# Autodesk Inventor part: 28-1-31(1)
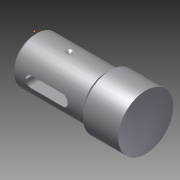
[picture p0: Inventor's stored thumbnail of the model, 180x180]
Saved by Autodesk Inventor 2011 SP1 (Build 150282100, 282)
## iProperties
Created: 2014-01
Part Number: 28-1-31(1)
Document SubType Name: Modeling
Designer: Administrator
Density: 1 g/cm^3
Author: Administrator
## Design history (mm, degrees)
sketch "草图1"
  geometry: L1 (0, 0)-(0, 9); L2 (0, 9)-(1.414, 10.414); L3 (1.414, 10.414)-(32.414, 10.414); L4 (32.414, 10.414)-(32.414, 8.414); L5 (32.414, 8.414)-(34.414, 8.414); L6 (34.414, 8.414)-(34.414, 12.414); L7 (34.414, 12.414)-(50.414, 12.414); L8 (50.414, 12.414)-(50.414, 0); L9 (50.414, 0)-(0, 0)
  constraints: 18 end point, 4 perpendicular, 3 parallel, 1 vertical
  dimensions: "d0" = 9 distance of L1.start L1.end; "d1" = 2 distance of L1.end L2.end; "d2" = 135 deg angle of L1 L2; "d3" = 31 distance of L2.end L3.end; "d4" = 2 distance of L3.end L4.end; "d5" = 2 distance of L4.end L5.end; "d6" = 4 distance of L5.end L6.end; "d7" = 16 distance of L6.end L7.end
revolve "旋转1" sketch "草图1" stored, may be unused: angle "d8" = 90 deg
node "工作平面2"
sketch "草图3"
  geometry: L1 (0, 9)-(0, -9) reference; L2 (-9, -2.5)-(-16, -2.5); L3 (-16, 2.5)-(-9, 2.5); L4 (-23, -2.5)-(-16, -2.5); L5 (-16, 2.5)-(-23, 2.5); A1 r 2.5 centre (-9, 0) between (-9, -2.5) and (-9, 2.5); A2 r 2.5 centre (-23, 0) between (-23, 2.5) and (-23, -2.5); 1 further point
  constraints: 8 end point, 4 point on circle, 2 centre point, 1 parallel, 1 perpendicular, 1 tangent
  dimensions: "d16" = 5 diameter of A1; "d17" = 7 distance of L2.start L2.end; "d18" = 9 distance from line of A1.centre L1
extrude "拉伸2" cut sketch "草图3" stored distance "d19" = 10; taper "d20" = 0 deg
node "工作平面3"
sketch "草图4"
  geometry: 2 further points
  dimensions: "d22" = 16 distance of point (0, 0) point (16, 0)
node "工作平面4"
sketch "草图5"
  geometry: 2 further points
hole "Hole1" sketch "草图5" at (16, 0) diameter "d24" = 3; stored, may be unused: countersink angle "d28" = 90 deg, drill point angle "d30" = 120 deg; dims "d25" = 6, "d26" = 4, "d27" = 2, "d29" = 1
sketch "草图6"
  geometry: 1 further point
node "实体1"
other parameters: "d21" = 10.414, "d23" = 1
